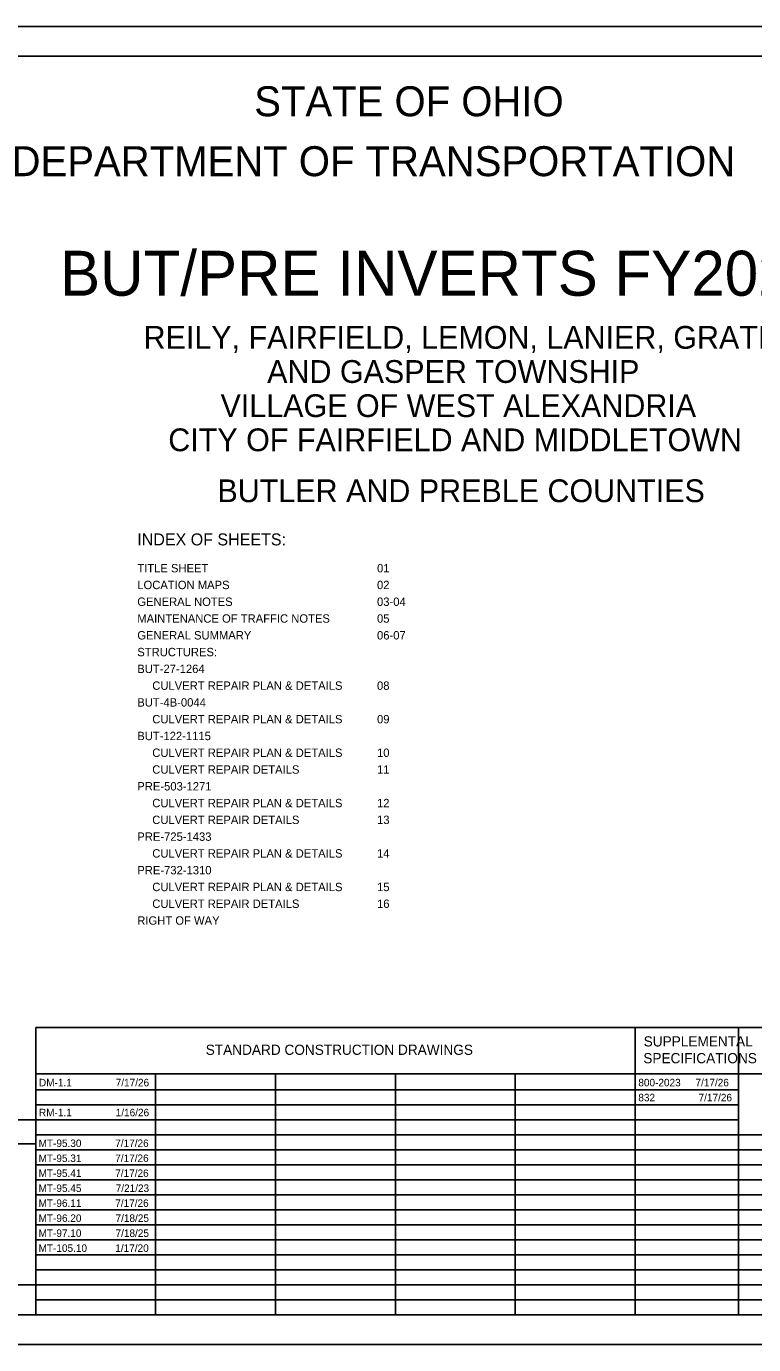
# Model space of a CAD drawing. Extents: x 0 to 34, y 0 to 22.
# Drawn here: x 9.99 to 22.13, y 0 to 22 of the extents above; entities that cross this region are included whole.
import ezdxf

# ---------------------------------------------------------------- set-up
doc = ezdxf.new("R2010")
doc.units = 0
for name, color, linetype in [('SH_Border', 7, 'Continuous'), ('SH_Cut_Line', 7, 'Continuous'), ('SH_Data', 7, 'Continuous'), ('SH_Text', 7, 'Continuous')]:
    doc.layers.add(name, color=color, linetype=linetype)

msp = doc.modelspace()

# ---------------------------------------------------------------- linework, layer by layer
at = {"layer": 'SH_Border'}
msp.add_lwpolyline([(1.5, 21.5), (33.5, 21.5), (33.5, 0.5), (1.5, 0.5)], close=True, dxfattribs=at)
at = {"layer": 'SH_Cut_Line'}
msp.add_lwpolyline([(0, 0), (34, 0), (34, 22), (0, 22)], close=True, dxfattribs=at)
at = {"layer": 'SH_Data'}
for p, q in [((10.15, 5.292), (23.6, 5.292)), ((10.15, 0.5), (10.15, 5.292)), ((20.15, 0.5), (20.15, 5.292)), ((21.875, 0.5), (21.875, 5.292)), ((10.15, 4.521), (23.6, 4.521)), ((12.15, 0.5), (12.15, 4.521)), ((14.15, 0.5), (14.15, 4.521)), ((16.15, 0.5), (16.15, 4.521)), ((18.15, 0.5), (18.15, 4.521)), ((10.15, 4.25), (21.875, 4.25)), ((10.15, 4), (21.875, 4)), ((10.15, 3.75), (7.35, 3.75)), ((10.15, 3.75), (21.875, 3.75)), ((10.15, 0.5), (10.15, 3.75)), ((10.15, 3.35), (7.35, 3.35)), ((10.15, 3.5), (23.6, 3.5)), ((10.15, 3.25), (23.6, 3.25)), ((10.15, 3), (23.6, 3)), ((10.15, 2.75), (23.6, 2.75)), ((10.15, 2.5), (23.6, 2.5)), ((10.15, 2.25), (23.6, 2.25)), ((10.15, 2), (23.6, 2)), ((10.15, 1.75), (23.6, 1.75)), ((10.15, 1.5), (23.6, 1.5)), ((10.15, 1.25), (23.6, 1.25)), ((10.15, 1), (23.6, 1)), ((10.15, 0.75), (23.6, 0.75)), ((10.15, 0.5), (7.35, 0.5))]:
    msp.add_line(p, q, dxfattribs=at)
msp.add_lwpolyline([(10.15, 0.5), (10.15, 1), (7.35, 1), (7.35, 0.5)], close=True, dxfattribs=at)

# ---------------------------------------------------------------- texts
at = {"layer": 'SH_Text'}
for s, height, p in [('STATE OF OHIO', 0.5, (13.795, 20.5)), ('DEPARTMENT OF TRANSPORTATION', 0.5, (9.747, 19.5)), ('BUT/PRE INVERTS FY2027', 0.75, (10.556, 17.505)), ('REILY, FAIRFIELD, LEMON, LANIER, GRATIS ', 0.38, (11.949, 16.62)), ('AND GASPER TOWNSHIP', 0.38, (14.011, 16.05)), ('VILLAGE OF WEST ALEXANDRIA', 0.38, (13.233, 15.48)), ('CITY OF FAIRFIELD AND MIDDLETOWN', 0.38, (12.361, 14.91)), ('BUTLER AND PREBLE COUNTIES', 0.38, (13.181, 14.06)), ('INDEX OF SHEETS:', 0.2, (11.844, 13.338)), ('TITLE SHEET', 0.14, (11.844, 12.888)), ('01', 0.14, (15.844, 12.888)), ('LOCATION MAPS', 0.14, (11.844, 12.608)), ('02', 0.14, (15.844, 12.608)), ('GENERAL NOTES', 0.14, (11.844, 12.328)), ('03-04', 0.14, (15.844, 12.328)), ('MAINTENANCE OF TRAFFIC NOTES', 0.14, (11.844, 12.048)), ('05', 0.14, (15.844, 12.048)), ('GENERAL SUMMARY', 0.14, (11.844, 11.768)), ('06-07', 0.14, (15.844, 11.768)), ('STRUCTURES:', 0.14, (11.844, 11.488)), ('BUT-27-1264', 0.14, (11.844, 11.208)), ('CULVERT REPAIR PLAN & DETAILS', 0.14, (12.094, 10.928)), ('08', 0.14, (15.844, 10.928)), ('BUT-4B-0044', 0.14, (11.844, 10.648)), ('CULVERT REPAIR PLAN & DETAILS', 0.14, (12.094, 10.368)), ('09', 0.14, (15.844, 10.368)), ('BUT-122-1115', 0.14, (11.844, 10.088)), ('CULVERT REPAIR PLAN & DETAILS', 0.14, (12.094, 9.808)), ('10', 0.14, (15.844, 9.808)), ('CULVERT REPAIR DETAILS', 0.14, (12.094, 9.528)), ('11', 0.14, (15.844, 9.528)), ('PRE-503-1271', 0.14, (11.844, 9.248)), ('CULVERT REPAIR PLAN & DETAILS', 0.14, (12.094, 8.968)), ('12', 0.14, (15.844, 8.968)), ('CULVERT REPAIR DETAILS', 0.14, (12.094, 8.688)), ('13', 0.14, (15.844, 8.688)), ('PRE-725-1433', 0.14, (11.844, 8.408)), ('CULVERT REPAIR PLAN & DETAILS', 0.14, (12.094, 8.128)), ('14', 0.14, (15.844, 8.128)), ('PRE-732-1310', 0.14, (11.844, 7.848)), ('CULVERT REPAIR PLAN & DETAILS', 0.14, (12.094, 7.568)), ('15', 0.14, (15.844, 7.568)), ('CULVERT REPAIR DETAILS', 0.14, (12.094, 7.288)), ('16', 0.14, (15.844, 7.288)), ('RIGHT OF WAY', 0.14, (11.844, 7.008)), ('SUPPLEMENTAL', 0.17, (20.293, 4.976)), ('STANDARD CONSTRUCTION DRAWINGS', 0.17, (12.986, 4.836)), ('SPECIFICATIONS', 0.17, (20.287, 4.696)), ('DM-1.1', 0.125, (10.204, 4.311)), ('7/17/26', 0.125, (11.484, 4.311)), ('800-2023', 0.125, (20.204, 4.311)), ('7/17/26', 0.125, (21.157, 4.311)), ('832', 0.125, (20.204, 4.061)), ('7/17/26', 0.125, (21.209, 4.061)), ('RM-1.1', 0.125, (10.204, 3.811)), ('1/16/26', 0.125, (11.484, 3.811)), ('MT-95.30', 0.125, (10.197, 3.298)), ('7/17/26', 0.125, (11.476, 3.298)), ('MT-95.31', 0.125, (10.197, 3.048)), ('7/17/26', 0.125, (11.476, 3.048)), ('MT-95.41', 0.125, (10.197, 2.798)), ('7/17/26', 0.125, (11.476, 2.798)), ('MT-95.45', 0.125, (10.197, 2.548)), ('7/21/23', 0.125, (11.484, 2.548)), ('MT-96.11', 0.125, (10.197, 2.298)), ('7/17/26', 0.125, (11.476, 2.298)), ('MT-96.20', 0.125, (10.197, 2.048)), ('7/18/25', 0.125, (11.481, 2.048)), ('MT-97.10', 0.125, (10.197, 1.798)), ('7/18/25', 0.125, (11.481, 1.798)), ('MT-105.10', 0.125, (10.197, 1.548)), ('1/17/20', 0.125, (11.477, 1.548))]:
    msp.add_text(s, height=height, dxfattribs=at).set_placement(p)

doc.saveas('drawing.dxf')
